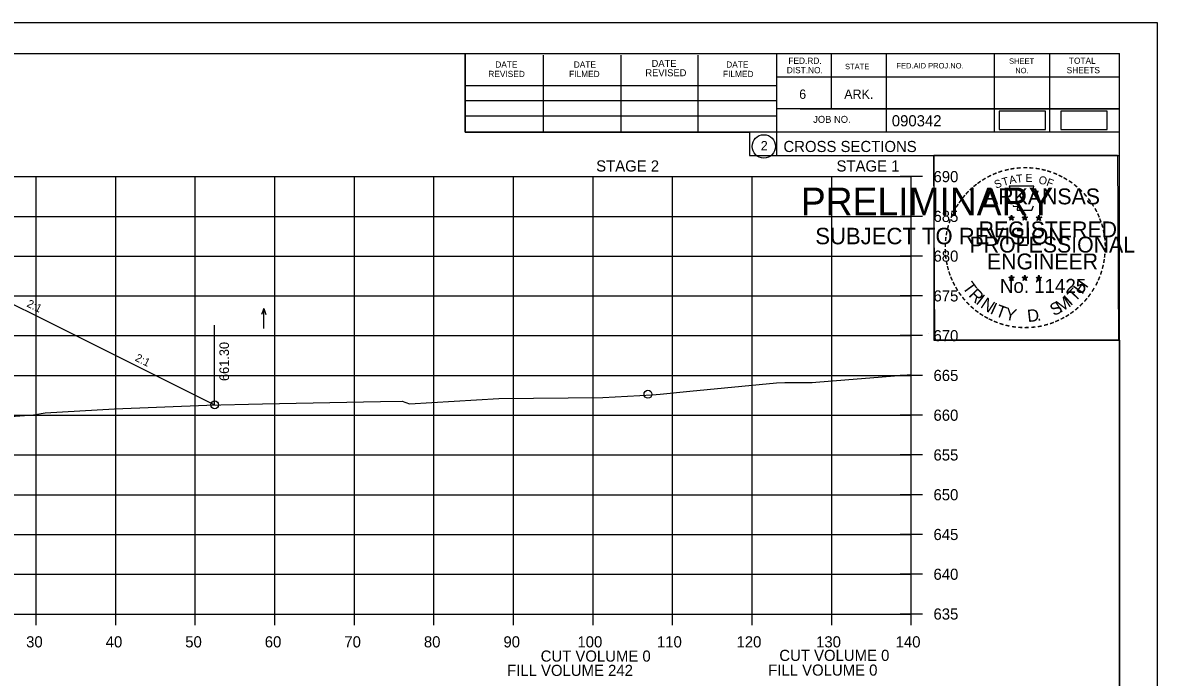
# Model space of a CAD drawing. Extents: x 1370515 to 1370849, y 383299 to 386073.
# Drawn here: x 1370706.1 to 1370848.7, y 384283.8 to 384366.1 of the extents above; entities that cross this region are included whole.
import ezdxf

# ---------------------------------------------------------------- set-up
doc = ezdxf.new("R2010")
doc.units = 0
for name, color, linetype in [('R_Axis', 7, 'Continuous'), ('R_Axis Annot', 7, 'Continuous'), ('R_Border', 7, 'Continuous'), ('R_Border PE', 7, 'Continuous'), ('R_Border Prem', 7, 'Continuous'), ('R_Detour', 7, 'Continuous'), ('R_Exist Surface', 7, 'Continuous'), ('R_Fin Surface', 7, 'Continuous'), ('R_Grid', 7, 'Continuous'), ('R_No Plot', 7, 'Continuous'), ('R_Water Annot', 7, 'Continuous'), ('R_Xsect Elev', 7, 'Continuous'), ('R_Xsect Slope', 7, 'Continuous')]:
    doc.layers.add(name, color=color, linetype=linetype)

msp = doc.modelspace()

# ---------------------------------------------------------------- linework, layer by layer
at = {"layer": 'R_Axis'}
for p, q in [((1370819.2, 384346.76), (1370816.4, 384346.76)), ((1370817.8, 384291.76), (1370817.8, 384346.76)), ((1370819.2, 384341.76), (1370816.4, 384341.76)), ((1370819.2, 384336.76), (1370816.4, 384336.76)), ((1370819.2, 384331.76), (1370816.4, 384331.76)), ((1370819.2, 384326.76), (1370816.4, 384326.76)), ((1370819.2, 384321.76), (1370816.4, 384321.76)), ((1370819.2, 384316.76), (1370816.4, 384316.76)), ((1370819.2, 384311.76), (1370816.4, 384311.76)), ((1370819.2, 384306.76), (1370816.4, 384306.76)), ((1370819.2, 384301.76), (1370816.4, 384301.76)), ((1370819.2, 384296.76), (1370816.4, 384296.76)), ((1370707.8, 384290.36), (1370707.8, 384293.16)), ((1370717.8, 384290.36), (1370717.8, 384293.16)), ((1370727.8, 384290.36), (1370727.8, 384293.16)), ((1370737.8, 384290.36), (1370737.8, 384293.16)), ((1370747.8, 384290.36), (1370747.8, 384293.16)), ((1370757.8, 384290.36), (1370757.8, 384293.16)), ((1370767.8, 384290.36), (1370767.8, 384293.16)), ((1370777.8, 384290.36), (1370777.8, 384293.16)), ((1370787.8, 384290.36), (1370787.8, 384293.16)), ((1370797.8, 384290.36), (1370797.8, 384293.16)), ((1370807.8, 384290.36), (1370807.8, 384293.16)), ((1370817.8, 384290.36), (1370817.8, 384293.16)), ((1370537.8, 384291.76), (1370817.8, 384291.76)), ((1370819.2, 384291.76), (1370816.4, 384291.76))]:
    msp.add_line(p, q, dxfattribs=at)
at = {"layer": 'R_Border'}
for p, q in [((1370527.8, 384362.22), (1370843.98, 384362.22)), ((1370761.72, 384352.34), (1370761.72, 384362.22)), ((1370771.58, 384352.34), (1370771.58, 384362.02)), ((1370781.34, 384352.34), (1370781.34, 384362.02)), ((1370791.02, 384352.34), (1370791.02, 384362.02)), ((1370800.88, 384362.22), (1370800.88, 384349.42)), ((1370807.72, 384362.22), (1370807.72, 384355.28)), ((1370814.66, 384362.22), (1370814.66, 384352.34)), ((1370828.24, 384362.22), (1370828.24, 384352.34)), ((1370835.18, 384362.22), (1370835.18, 384352.34)), ((1370843.98, 384156.76), (1370843.98, 384362.22)), ((1370761.72, 384358.2), (1370800.88, 384358.2)), ((1370843.98, 384359.28), (1370800.88, 384359.28)), ((1370843.98, 384359.3), (1370843.98, 384359.3)), ((1370761.72, 384356.34), (1370800.88, 384356.34)), ((1370843.98, 384355.28), (1370800.88, 384355.28)), ((1370803.84, 384355.28), (1370843.98, 384355.28)), ((1370761.72, 384352.34), (1370761.72, 384354.4)), ((1370761.72, 384354.4), (1370800.88, 384354.4)), ((1370843.98, 384352.34), (1370761.72, 384352.34)), ((1370800.88, 384349.42), (1370843.98, 384349.42))]:
    msp.add_line(p, q, dxfattribs=at)
msp.add_circle((1370799.27, 384350.56), 1.47, dxfattribs=at)
at = {"layer": 'R_Border PE'}
for p, q in [((1370830.07, 384341.68), (1370830.42, 384341.56)), ((1370830.07, 384341.68), (1370830.32, 384341.63)), ((1370830.07, 384341.68), (1370830.3, 384341.55)), ((1370830.2, 384341.27), (1370830.42, 384341.56)), ((1370830.2, 384341.27), (1370830.33, 384341.51)), ((1370830.2, 384341.27), (1370830.41, 384341.48)), ((1370830.42, 384341.93), (1370830.37, 384341.68)), ((1370830.63, 384341.27), (1370830.41, 384341.48)), ((1370830.42, 384341.56), (1370830.42, 384341.93)), ((1370830.42, 384341.93), (1370830.46, 384341.68)), ((1370830.76, 384341.68), (1370830.42, 384341.56)), ((1370830.63, 384341.27), (1370830.42, 384341.56)), ((1370830.76, 384341.68), (1370830.48, 384341.63)), ((1370830.63, 384341.27), (1370830.49, 384341.56)), ((1370830.76, 384341.68), (1370830.56, 384341.57)), ((1370831.74, 384341.68), (1370832.09, 384341.56)), ((1370831.74, 384341.68), (1370831.99, 384341.63)), ((1370831.74, 384341.68), (1370831.97, 384341.55)), ((1370831.87, 384341.27), (1370832.09, 384341.56)), ((1370831.87, 384341.27), (1370832, 384341.51)), ((1370831.87, 384341.27), (1370832.08, 384341.48)), ((1370832.09, 384341.93), (1370832.04, 384341.68)), ((1370832.3, 384341.27), (1370832.08, 384341.48)), ((1370832.09, 384341.56), (1370832.09, 384341.93)), ((1370832.09, 384341.93), (1370832.13, 384341.68)), ((1370832.43, 384341.68), (1370832.09, 384341.56)), ((1370832.3, 384341.27), (1370832.09, 384341.56)), ((1370832.43, 384341.68), (1370832.15, 384341.63)), ((1370832.3, 384341.27), (1370832.16, 384341.56)), ((1370832.43, 384341.68), (1370832.23, 384341.57)), ((1370833.5, 384341.66), (1370833.85, 384341.55)), ((1370833.5, 384341.66), (1370833.75, 384341.62)), ((1370833.5, 384341.66), (1370833.74, 384341.54)), ((1370833.63, 384341.26), (1370833.85, 384341.55)), ((1370833.63, 384341.26), (1370833.76, 384341.5)), ((1370833.63, 384341.26), (1370833.85, 384341.47)), ((1370833.85, 384341.92), (1370833.81, 384341.67)), ((1370833.85, 384341.55), (1370833.85, 384341.92)), ((1370833.85, 384341.92), (1370833.9, 384341.67)), ((1370834.2, 384341.66), (1370833.85, 384341.55)), ((1370834.06, 384341.26), (1370833.85, 384341.55)), ((1370834.06, 384341.26), (1370833.85, 384341.47)), ((1370834.2, 384341.66), (1370833.91, 384341.61)), ((1370834.06, 384341.26), (1370833.93, 384341.55)), ((1370834.2, 384341.66), (1370833.99, 384341.56)), ((1370830.06, 384334.1), (1370830.41, 384333.99)), ((1370830.06, 384334.1), (1370830.32, 384334.06)), ((1370830.06, 384334.1), (1370830.3, 384333.98)), ((1370830.2, 384333.69), (1370830.41, 384333.99)), ((1370830.2, 384333.69), (1370830.32, 384333.94)), ((1370830.2, 384333.69), (1370830.41, 384333.91)), ((1370830.41, 384334.36), (1370830.37, 384334.1)), ((1370830.41, 384333.99), (1370830.41, 384334.36)), ((1370830.41, 384334.36), (1370830.46, 384334.11)), ((1370830.76, 384334.1), (1370830.41, 384333.99)), ((1370830.62, 384333.69), (1370830.41, 384333.99)), ((1370830.62, 384333.69), (1370830.41, 384333.91)), ((1370830.76, 384334.1), (1370830.47, 384334.05)), ((1370830.62, 384333.69), (1370830.49, 384333.99)), ((1370830.76, 384334.1), (1370830.55, 384334)), ((1370831.73, 384334.1), (1370832.08, 384333.99)), ((1370831.73, 384334.1), (1370831.98, 384334.06)), ((1370831.73, 384334.1), (1370831.97, 384333.98)), ((1370831.86, 384333.69), (1370832.08, 384333.99)), ((1370831.86, 384333.69), (1370831.99, 384333.94)), ((1370831.86, 384333.69), (1370832.08, 384333.91)), ((1370832.08, 384334.36), (1370832.04, 384334.1)), ((1370832.08, 384333.99), (1370832.08, 384334.36)), ((1370832.08, 384334.36), (1370832.13, 384334.11)), ((1370832.43, 384334.1), (1370832.08, 384333.99)), ((1370832.29, 384333.69), (1370832.08, 384333.99)), ((1370832.29, 384333.69), (1370832.08, 384333.91)), ((1370832.43, 384334.1), (1370832.14, 384334.05)), ((1370832.29, 384333.69), (1370832.16, 384333.99)), ((1370832.43, 384334.1), (1370832.22, 384334)), ((1370833.5, 384334.09), (1370833.85, 384333.98)), ((1370833.5, 384334.09), (1370833.75, 384334.05)), ((1370833.5, 384334.09), (1370833.74, 384333.97)), ((1370833.63, 384333.68), (1370833.85, 384333.98)), ((1370833.63, 384333.68), (1370833.76, 384333.93)), ((1370833.63, 384333.68), (1370833.85, 384333.9)), ((1370833.85, 384334.35), (1370833.81, 384334.09)), ((1370833.85, 384333.98), (1370833.85, 384334.35)), ((1370833.85, 384334.35), (1370833.9, 384334.1)), ((1370834.19, 384334.09), (1370833.85, 384333.98)), ((1370834.06, 384333.68), (1370833.85, 384333.98)), ((1370834.06, 384333.68), (1370833.85, 384333.9)), ((1370834.19, 384334.09), (1370833.91, 384334.04)), ((1370834.06, 384333.68), (1370833.92, 384333.98)), ((1370834.19, 384334.09), (1370833.99, 384333.99))]:
    msp.add_line(p, q, dxfattribs=at)
for points in [[(1370830.11, 384345.55), (1370830.38, 384344.73)], [(1370833.62, 384344.63), (1370833.76, 384344.92), (1370833.08, 384344.89), (1370833.22, 384345.55), (1370830.11, 384345.55)], [(1370830.6, 384343.13), (1370830.6, 384343.04), (1370831.16, 384343.02), (1370831.11, 384342.55), (1370832.98, 384342.55), (1370833.18, 384343.09)], [(1370830.42, 384341.93), (1370830.63, 384341.27), (1370830.07, 384341.68), (1370830.76, 384341.68), (1370830.2, 384341.27), (1370830.42, 384341.93)], [(1370832.09, 384341.93), (1370832.3, 384341.27), (1370831.74, 384341.68), (1370832.43, 384341.68), (1370831.87, 384341.27), (1370832.09, 384341.93)], [(1370833.85, 384341.92), (1370834.06, 384341.26), (1370833.5, 384341.66), (1370834.2, 384341.66), (1370833.63, 384341.26), (1370833.85, 384341.92)], [(1370830.41, 384334.36), (1370830.62, 384333.69), (1370830.06, 384334.1), (1370830.76, 384334.1), (1370830.2, 384333.69), (1370830.41, 384334.36)], [(1370832.08, 384334.36), (1370832.29, 384333.69), (1370831.73, 384334.1), (1370832.43, 384334.1), (1370831.86, 384333.69), (1370832.08, 384334.36)], [(1370833.85, 384334.35), (1370834.06, 384333.68), (1370833.5, 384334.09), (1370834.19, 384334.09), (1370833.63, 384333.68), (1370833.85, 384334.35)]]:
    msp.add_lwpolyline(points, dxfattribs=at)
for centre, radius in [((1370830.41, 384341.56), 0.172), ((1370830.41, 384341.56), 0.145), ((1370830.41, 384341.56), 0.116), ((1370830.41, 384341.56), 0.0991), ((1370830.41, 384341.56), 0.0747), ((1370830.41, 384341.56), 0.0495), ((1370830.41, 384341.56), 0.0296), ((1370832.08, 384341.56), 0.172), ((1370832.08, 384341.56), 0.145), ((1370832.08, 384341.56), 0.116), ((1370832.08, 384341.56), 0.0991), ((1370832.08, 384341.56), 0.0747), ((1370832.08, 384341.56), 0.0495), ((1370832.08, 384341.56), 0.0296), ((1370833.85, 384341.55), 0.172), ((1370833.85, 384341.55), 0.145), ((1370833.85, 384341.55), 0.116), ((1370833.85, 384341.55), 0.0991), ((1370833.85, 384341.55), 0.0747), ((1370833.85, 384341.55), 0.0495), ((1370833.85, 384341.55), 0.0296), ((1370830.41, 384333.99), 0.172), ((1370830.41, 384333.99), 0.145), ((1370830.41, 384333.99), 0.116), ((1370830.41, 384333.99), 0.0991), ((1370830.41, 384333.99), 0.0747), ((1370830.41, 384333.99), 0.0495), ((1370830.41, 384333.99), 0.0296), ((1370832.08, 384333.99), 0.172), ((1370832.08, 384333.99), 0.145), ((1370832.08, 384333.99), 0.116), ((1370832.08, 384333.99), 0.0991), ((1370832.08, 384333.99), 0.0747), ((1370832.08, 384333.99), 0.0495), ((1370832.08, 384333.99), 0.0296), ((1370833.85, 384333.98), 0.172), ((1370833.85, 384333.98), 0.145), ((1370833.85, 384333.98), 0.116), ((1370833.85, 384333.98), 0.0991), ((1370833.85, 384333.98), 0.0747), ((1370833.85, 384333.98), 0.0495), ((1370833.85, 384333.98), 0.0296)]:
    msp.add_circle(centre, radius, dxfattribs=at)
at = {"layer": 'R_Detour'}
for points in [[(1370828.87, 384352.68), (1370834.7, 384352.68), (1370834.7, 384354.99), (1370828.87, 384354.99)], [(1370836.61, 384352.68), (1370842.45, 384352.68), (1370842.45, 384354.99), (1370836.61, 384354.99)]]:
    msp.add_lwpolyline(points, close=True, dxfattribs=at)
at = {"layer": 'R_Exist Surface'}
msp.add_lwpolyline([(1370701.08, 384316.36), (1370707.48, 384316.79), (1370708.94, 384317.05), (1370717.63, 384317.56), (1370729.25, 384318.03), (1370736.26, 384318.2), (1370751.07, 384318.48), (1370753.83, 384318.54), (1370754.73, 384318.18), (1370765.97, 384318.86), (1370779.03, 384319), (1370785.24, 384319.34), (1370786.23, 384319.39), (1370789.98, 384319.76), (1370800.88, 384320.82), (1370801.9, 384320.88), (1370805.15, 384320.89), (1370805.25, 384320.88), (1370805.34, 384320.89), (1370805.79, 384320.93), (1370817.8, 384321.86)], dxfattribs=at)
at = {"layer": 'R_Fin Surface'}
msp.add_lwpolyline([(1370602.99, 384310.44), (1370651.8, 384334.85), (1370657.8, 384336.35), (1370665.8, 384335.63), (1370677.8, 384334.56), (1370689.8, 384333.49), (1370697.8, 384332.78), (1370703.8, 384331.28), (1370708.83, 384328.76), (1370730.24, 384318.06)], dxfattribs=at)
at = {"layer": 'R_Grid'}
for p, q in [((1370537.8, 384346.76), (1370817.8, 384346.76)), ((1370707.8, 384291.76), (1370707.8, 384346.76)), ((1370717.8, 384291.76), (1370717.8, 384346.76)), ((1370727.8, 384291.76), (1370727.8, 384346.76)), ((1370737.8, 384291.76), (1370737.8, 384346.76)), ((1370747.8, 384291.76), (1370747.8, 384346.76)), ((1370757.8, 384291.76), (1370757.8, 384346.76)), ((1370767.8, 384291.76), (1370767.8, 384346.76)), ((1370777.8, 384291.76), (1370777.8, 384346.76)), ((1370787.8, 384291.76), (1370787.8, 384346.76)), ((1370797.8, 384291.76), (1370797.8, 384346.76)), ((1370807.8, 384291.76), (1370807.8, 384346.76)), ((1370817.8, 384291.76), (1370817.8, 384346.76)), ((1370537.8, 384341.76), (1370817.8, 384341.76)), ((1370537.8, 384336.76), (1370817.8, 384336.76)), ((1370537.8, 384331.76), (1370817.8, 384331.76)), ((1370537.8, 384326.76), (1370817.8, 384326.76)), ((1370537.8, 384321.76), (1370817.8, 384321.76)), ((1370537.8, 384316.76), (1370817.8, 384316.76)), ((1370537.8, 384311.76), (1370817.8, 384311.76)), ((1370537.8, 384306.76), (1370817.8, 384306.76)), ((1370537.8, 384301.76), (1370817.8, 384301.76)), ((1370537.8, 384296.76), (1370817.8, 384296.76)), ((1370537.8, 384291.76), (1370817.8, 384291.76))]:
    msp.add_line(p, q, dxfattribs=at)
at = {"layer": 'R_No Plot'}
for p, q in [((1370515.4, 384366.12), (1370848.73, 384366.12)), ((1370820.02, 384326.97), (1370820.02, 384326.97))]:
    msp.add_line(p, q, dxfattribs=at)
for points in [[(1370515.39, 384366.12), (1370848.73, 384366.12), (1370848.73, 384152.78), (1370515.39, 384152.78)], [(1370761.72, 384362.22), (1370761.72, 384352.34), (1370797.45, 384352.34), (1370797.45, 384349.42), (1370820.65, 384349.42), (1370820.65, 384326.21), (1370843.98, 384326.21), (1370843.98, 384156.76), (1370527.8, 384156.76), (1370527.8, 384362.22)], [(1370820.65, 384349.45), (1370843.75, 384349.45), (1370843.87, 384326.21), (1370820.77, 384326.21)]]:
    msp.add_lwpolyline(points, close=True, dxfattribs=at)
for centre in [(1370784.71, 384319.39), (1370730.24, 384318.06)]:
    msp.add_circle(centre, 0.5, dxfattribs=at)
at = {"layer": 'R_Water Annot'}
for p, q in [((1370736.4, 384330.19), (1370736.12, 384329.42)), ((1370736.4, 384327.67), (1370736.4, 384330.19)), ((1370736.4, 384330.19), (1370736.68, 384329.42))]:
    msp.add_line(p, q, dxfattribs=at)
at = {"layer": 'R_Xsect Elev'}
msp.add_line((1370730.24, 384318.06), (1370730.24, 384328.06), dxfattribs=at)

# ---------------------------------------------------------------- texts
at = {"layer": 'R_Axis Annot'}
for s, p in [('STAGE 2', (1370778.2, 384347.4)), ('STAGE 1', (1370808.41, 384347.4)), ('690', (1370820.6, 384346.06)), ('685', (1370820.6, 384341.06)), ('680', (1370820.6, 384336.06)), ('675', (1370820.6, 384331.06)), ('670', (1370820.6, 384326.06)), ('665', (1370820.6, 384321.06)), ('660', (1370820.6, 384316.06)), ('655', (1370820.6, 384311.06)), ('650', (1370820.6, 384306.06)), ('645', (1370820.6, 384301.06)), ('640', (1370820.6, 384296.06)), ('635', (1370820.6, 384291.06)), ('30', (1370706.54, 384287.56)), ('40', (1370716.54, 384287.56)), ('50', (1370726.54, 384287.56)), ('60', (1370736.54, 384287.56)), ('70', (1370746.54, 384287.56)), ('80', (1370756.54, 384287.56)), ('90', (1370766.54, 384287.56)), ('100', (1370775.84, 384287.56)), ('110', (1370785.84, 384287.56)), ('120', (1370795.84, 384287.56)), ('130', (1370805.84, 384287.56)), ('140', (1370815.84, 384287.56)), ('CUT VOLUME 0', (1370771.22, 384285.77)), ('CUT VOLUME 0', (1370801.22, 384285.86)), ('FILL VOLUME 242', (1370767, 384283.97)), ('FILL VOLUME 0', (1370799.82, 384284.01))]:
    msp.add_text(s, height=1.4, dxfattribs=at).set_placement(p)
at = {"layer": 'R_Border'}
for s, height, p in [('DATE', 0.782, (1370765.52, 384360.46)), ('DATE', 0.782, (1370775.38, 384360.46)), ('DATE', 0.879, (1370785.16, 384360.56)), ('DATE', 0.782, (1370794.54, 384360.46)), ('FED.RD.', 0.782, (1370802.36, 384360.94)), ('STATE', 0.684, (1370809.48, 384360.26)), ('FED.AID PROJ.NO.', 0.684, (1370815.94, 384360.36)), ('SHEET', 0.684, (1370830.1, 384360.94)), ('TOTAL', 0.782, (1370837.62, 384360.94)), ('REVISED', 0.782, (1370764.64, 384359.28)), ('FILMED', 0.782, (1370774.8, 384359.28)), ('REVISED', 0.879, (1370784.38, 384359.38)), ('FILMED', 0.782, (1370794.14, 384359.28)), ('DIST.NO.', 0.782, (1370802.16, 384359.76)), ('NO.', 0.684, (1370830.88, 384359.76)), ('SHEETS', 0.782, (1370837.34, 384359.76)), ('6', 1.17, (1370803.72, 384356.54)), ('ARK.', 1.172, (1370809.38, 384356.54)), ('JOB NO.', 0.879, (1370805.48, 384353.52)), ('090342', 1.4, (1370815.36, 384353.08)), ('2', 1.17, (1370798.89, 384350.07)), ('CROSS SECTIONS', 1.4, (1370801.74, 384349.85))]:
    msp.add_text(s, height=height, rotation=360, dxfattribs=at).set_placement(p)
at = {"layer": 'R_Border PE'}
for s, height, rotation, p in [('-', 1.6, 34.0636, (1370826.99, 384345.72)), ('-', 1.6, 28.7918, (1370827.59, 384346.09)), ('-', 1.6, 24.3072, (1370828.22, 384346.41)), ('-', 1.6, 19.1761, (1370828.86, 384346.68)), ('T', 1, 16.4036, (1370829.38, 384345.56)), ('-', 1.6, 13.6301, (1370829.61, 384346.92)), ('A', 1, 11.2132, (1370830.2, 384345.81)), ('-', 1.6, 10.2193, (1370830.28, 384347.08)), ('T', 1, 6.0228, (1370831.05, 384345.98)), ('-', 1.6, 5.8968, (1370831.01, 384347.19)), ('-', 1.6, 0.1862, (1370831.78, 384347.27)), ('E', 1, 0.8323, (1370832.16, 384346.09)), ('-', 1.6, 357.743, (1370832.51, 384347.25)), ('-', 1.6, 352.1617, (1370833.25, 384347.2)), ('O', 1, 350.4515, (1370833.76, 384345.88)), ('-', 1.6, 347.2049, (1370833.97, 384347.08)), ('-', 1.6, 342.3362, (1370834.61, 384346.93)), ('-', 1.6, 337.8551, (1370835.34, 384346.7)), ('-', 1.6, 334.1211, (1370835.97, 384346.43)), ('-', 1.6, 329.6409, (1370836.55, 384346.15)), ('-', 1.6, 42.9622, (1370825.5, 384344.53)), ('-', 1.6, 38.9507, (1370825.94, 384344.95)), ('-', 1.6, 36.2317, (1370826.41, 384345.33)), ('ARKANSAS', 2, 360, (1370826.96, 384343.27)), ('S', 1, 21.594, (1370828.46, 384345.23)), ('F', 1, 340.0707, (1370834.71, 384345.65)), ('-', 1.6, 325.8627, (1370837.19, 384345.79)), ('-', 1.6, 320.5297, (1370837.8, 384345.36)), ('-', 1.6, 315.5786, (1370838.4, 384344.88)), ('-', 1.6, 54.2325, (1370824.24, 384343)), ('-', 1.6, 50.6142, (1370824.65, 384343.57)), ('-', 1.6, 48.423, (1370825.06, 384344.06)), ('-', 1.6, 309.8797, (1370838.97, 384344.33)), ('-', 1.6, 306.6522, (1370839.5, 384343.72)), ('-', 1.6, 62.8713, (1370823.6, 384341.86)), ('-', 1.6, 58.0706, (1370823.92, 384342.48)), ('-', 1.4, 303.6753, (1370839.98, 384343.16)), ('-', 1.6, 299.6684, (1370840.3, 384342.55)), ('-', 1.6, 72.3945, (1370823.12, 384340.62)), ('-', 1.6, 67.7743, (1370823.34, 384341.25)), ('REGISTERED', 2, 360, (1370826.28, 384339.12)), ('DWB', 0.01, 360, (1370830.4, 384341.56)), ('DWB', 0.01, 360, (1370832.07, 384341.56)), ('DWB', 0.01, 360, (1370833.84, 384341.55)), ('-', 1.6, 294.6628, (1370840.63, 384341.94)), ('-', 1.6, 290.5728, (1370840.88, 384341.36)), ('-', 1.6, 81.2013, (1370822.8, 384339.19)), ('-', 1.6, 75.461, (1370822.93, 384339.91)), ('-', 1.6, 285.1233, (1370841.12, 384340.78)), ('-', 1.6, 280.5493, (1370841.32, 384340.04)), ('-', 1.6, 89.0622, (1370822.69, 384337.8)), ('-', 1.6, 85.1863, (1370822.72, 384338.5)), ('PROFESSIONAL', 2, 360, (1370825.13, 384337.21)), ('-', 1.6, 276.5962, (1370841.48, 384339.27)), ('-', 1.6, 274.3301, (1370841.54, 384338.55)), ('-', 1.6, 94.1959, (1370822.73, 384337.08)), ('-', 1.6, 98.9479, (1370822.8, 384336.41)), ('ENGINEER', 2, 360, (1370827.32, 384335.09)), ('-', 1.6, 263.5172, (1370841.55, 384337.25)), ('-', 1.6, 269.9407, (1370841.57, 384337.92)), ('-', 1.6, 101.7149, (1370822.94, 384335.68)), ('-', 1.6, 105.4578, (1370823.1, 384335.08)), ('-', 1.6, 255.7626, (1370841.37, 384335.92)), ('-', 1.6, 260.9953, (1370841.48, 384336.6)), ('-', 1.6, 109.0874, (1370823.31, 384334.45)), ('-', 1.6, 114.0643, (1370823.57, 384333.86)), ('No. 11425', 1.757, 360, (1370828.95, 384332.14)), ('DWB', 0.01, 360, (1370830.4, 384333.99)), ('DWB', 0.01, 360, (1370832.07, 384333.99)), ('DWB', 0.01, 360, (1370833.83, 384333.98)), ('H', 1.54, 54.6088, (1370839.29, 384331.87)), ('-', 1.6, 247.8887, (1370840.97, 384334.52)), ('-', 1.6, 252.8681, (1370841.19, 384335.2)), ('-', 1.6, 115.7288, (1370823.87, 384333.24)), ('-', 1.6, 120.4471, (1370824.23, 384332.65)), ('T', 1.54, 306.0406, (1370824.17, 384332.83)), ('R', 1.54, 314.005, (1370824.93, 384331.78)), ('T', 1.54, 46.6444, (1370838.4, 384330.92)), ('-', 1.6, 239.0712, (1370840.31, 384333.14)), ('-', 1.6, 244.6197, (1370840.71, 384333.9)), ('-', 1.6, 125.8934, (1370824.63, 384332.09)), ('-', 1.6, 130.7181, (1370825.09, 384331.54)), ('-', 1.6, 134.2238, (1370825.61, 384330.99)), ('I', 1.54, 321.9694, (1370825.83, 384330.85)), ('N', 1.54, 326.5002, (1370826.4, 384330.38)), ('I', 1.54, 335.3603, (1370827.61, 384329.59)), ('S', 1.54, 26.9312, (1370835.72, 384329.19)), ('M', 1.54, 32.6563, (1370836.56, 384329.6)), ('I', 1.54, 42.1136, (1370837.84, 384330.44)), ('-', 1.6, 225.7653, (1370839, 384331.36)), ('-', 1.6, 231.2538, (1370839.48, 384331.92)), ('-', 1.6, 233.8452, (1370839.91, 384332.49)), ('-', 1.6, 138.9338, (1370826.14, 384330.53)), ('-', 1.6, 144.6463, (1370826.69, 384330.12)), ('-', 1.6, 148.0898, (1370827.25, 384329.75)), ('T', 1.54, 339.8912, (1370828.27, 384329.27)), ('Y', 1.54, 347.8556, (1370829.49, 384328.82)), ('D', 1.54, 6.3969, (1370832.47, 384328.46)), ('-', 1.6, 212.2491, (1370837.4, 384329.99)), ('-', 1.6, 215.7363, (1370837.93, 384330.38)), ('-', 1.6, 221.0851, (1370838.48, 384330.85)), ('-', 1.6, 151.5704, (1370827.83, 384329.43)), ('-', 1.6, 154.6002, (1370828.35, 384329.18)), ('-', 1.6, 158.5612, (1370828.98, 384328.93)), ('-', 1.6, 162.7983, (1370829.67, 384328.71)), ('-', 1.6, 167.5555, (1370830.38, 384328.55)), ('-', 1.6, 191.2858, (1370834.19, 384328.61)), ('.', 1.54, 13.7642, (1370833.66, 384328.59)), ('-', 1.6, 195.4743, (1370834.92, 384328.81)), ('-', 1.6, 200.7184, (1370835.6, 384329.05)), ('-', 1.6, 204.2516, (1370836.21, 384329.33)), ('-', 1.6, 207.3568, (1370836.84, 384329.65)), ('-', 1.6, 173.1155, (1370831.15, 384328.44)), ('-', 1.6, 176.5183, (1370831.9, 384328.39)), ('-', 1.6, 181.5918, (1370832.64, 384328.41)), ('-', 1.6, 185.8167, (1370833.45, 384328.48))]:
    msp.add_text(s, height=height, rotation=rotation, dxfattribs=at).set_placement(p)
at = {"layer": 'R_Border Prem'}
for s, height, p in [('PRELIMINARY', 3.5, (1370803.93, 384341.88)), ('DWB', 0.01, (1370804.68, 384343.73)), ('SUBJECT TO REVISION', 2.0751, (1370805.74, 384338.25))]:
    msp.add_text(s, height=height, rotation=360, dxfattribs=at).set_placement(p)
at = {"layer": 'R_No Plot'}
for p in [(1370805.21, 384320.83), (1370778.98, 384318.95), (1370708.9, 384317)]:
    msp.add_text('+', height=0.1, dxfattribs=at).set_placement(p)
at = {"layer": 'R_Xsect Elev'}
msp.add_text('661.30', height=1.2, rotation=90, dxfattribs=at).set_placement((1370732.04, 384321.06))
at = {"layer": 'R_Xsect Slope'}
for p in [(1370706.54, 384330.47), (1370720.15, 384323.66)]:
    msp.add_text('2:1', height=1, rotation=333.4349, dxfattribs=at).set_placement(p)

doc.saveas('drawing.dxf')
